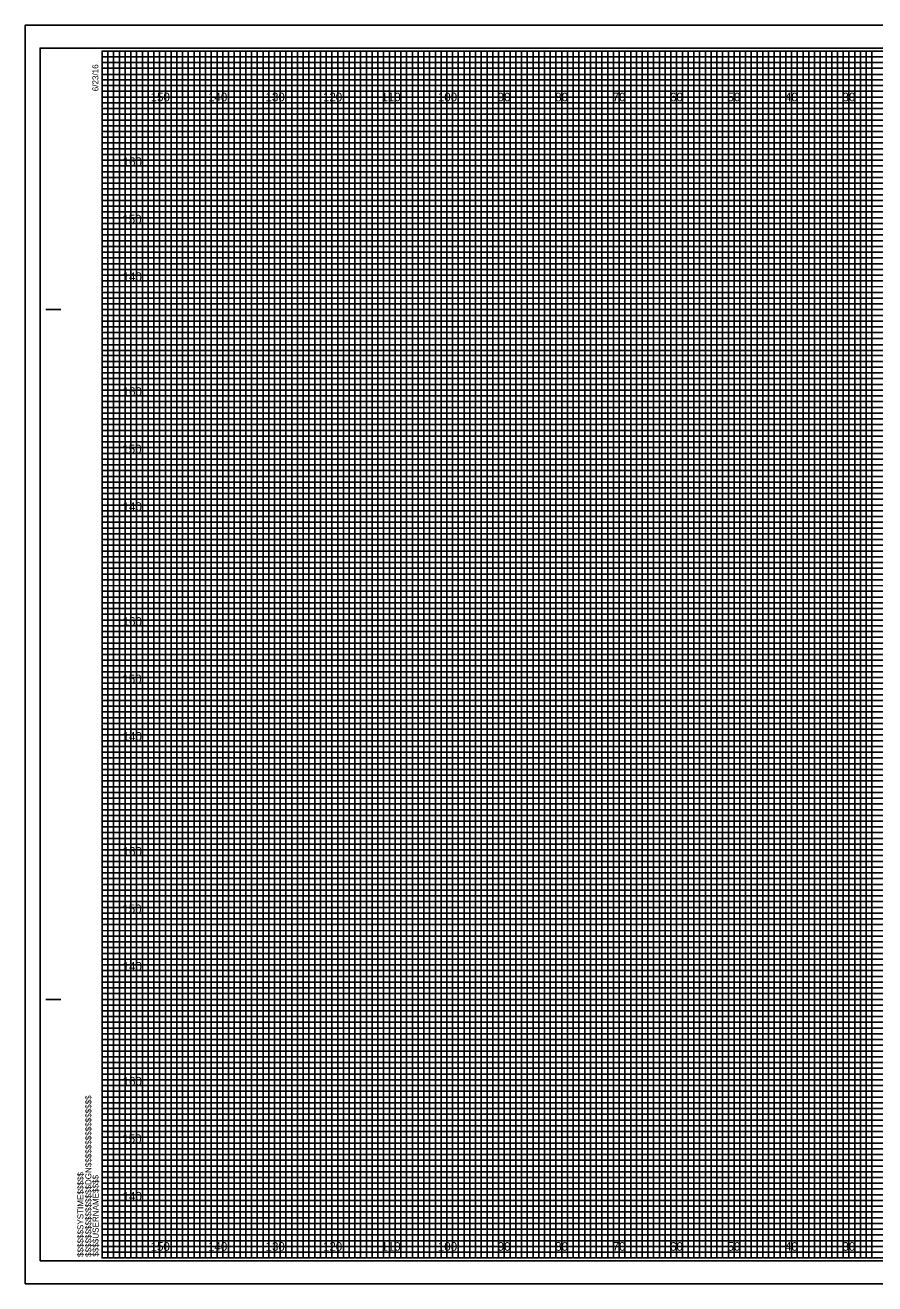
# Model space of a CAD drawing. Extents: x -13 to 323, y -5 to 4834.
# Drawn here: x -13.4 to 134.5, y -4.5 to 214.5 of the extents above; entities that cross this region are included whole.
import ezdxf

# ---------------------------------------------------------------- set-up
doc = ezdxf.new("R2010")
doc.units = 0
for name, color, linetype in [('Exist Cross Section Cell', 7, 'Continuous'), ('Exist XS Center Line Elevation Label', 7, 'Continuous'), ('Exist XS Ground Line', 7, 'Continuous'), ('Prop CMT Pvmt Course 1', 7, 'Continuous'), ('Prop CMT Pvmt Course 2', 7, 'Continuous'), ('Prop CMT Pvmt Course 3', 7, 'Continuous'), ('Prop CMT Pvmt Surface Shoulder', 7, 'Continuous'), ('Prop CMT Shld Paved Course 1', 7, 'Continuous'), ('Prop CMT Shld Paved Course 2', 7, 'Continuous'), ('Prop CMT Shld Paved Course 3', 7, 'Continuous'), ('Prop CMT Slope Grass', 7, 'Continuous')]:
    doc.layers.add(name, color=color, linetype=linetype)

msp = doc.modelspace()

# ---------------------------------------------------------------- linework, layer by layer
at = {"layer": 'Exist XS Center Line Elevation Label'}
for points in [[(0, 210), (5, 210), (5, 0), (15, 0), (15, 210), (25, 210), (25, 0), (35, 0), (35, 210), (45, 210), (45, 0), (55, 0), (55, 210), (65, 210), (65, 0), (75, 0), (75, 210), (85, 210), (85, 0), (95, 0), (95, 210), (105, 210), (105, 0), (115, 0), (115, 210), (125, 210), (125, 0), (135, 0)], [(0, 205), (275, 205)], [(0, 185), (320, 185), (320, 195), (0, 195)], [(0, 165), (320, 165), (320, 175), (0, 175)], [(0, 145), (320, 145), (320, 155), (0, 155)], [(0, 125), (320, 125), (320, 135), (0, 135)], [(0, 105), (320, 105), (320, 115), (0, 115)], [(0, 85), (320, 85), (320, 95), (0, 95)], [(0, 65), (320, 65), (320, 75), (0, 75)], [(0, 45), (320, 45), (320, 55), (0, 55)], [(0, 25), (320, 25), (320, 35), (0, 35)], [(0, 5), (320, 5), (320, 15), (0, 15)]]:
    msp.add_lwpolyline(points, dxfattribs=at)
at = {"layer": 'Exist XS Ground Line'}
for p, q in [((10, 210), (0, 210)), ((10, 0), (10, 210)), ((30, 210), (20, 210)), ((20, 210), (20, 0)), ((30, 0), (30, 210)), ((50, 210), (40, 210)), ((40, 210), (40, 0)), ((50, 0), (50, 210)), ((70, 210), (60, 210)), ((60, 210), (60, 0)), ((70, 0), (70, 210)), ((90, 210), (80, 210)), ((80, 210), (80, 0)), ((90, 0), (90, 210)), ((110, 210), (100, 210)), ((100, 210), (100, 0)), ((110, 0), (110, 210)), ((130, 210), (120, 210)), ((120, 210), (120, 0)), ((130, 0), (130, 210)), ((20, 0), (10, 0)), ((40, 0), (30, 0)), ((60, 0), (50, 0)), ((80, 0), (70, 0)), ((100, 0), (90, 0)), ((120, 0), (110, 0)), ((140, 0), (130, 0))]:
    msp.add_line(p, q, dxfattribs=at)
for points in [[(0, 200), (320, 200), (320, 190), (0, 190)], [(0, 180), (320, 180), (320, 170), (0, 170)], [(0, 160), (320, 160), (320, 150), (0, 150)], [(0, 140), (320, 140), (320, 130), (0, 130)], [(0, 120), (320, 120), (320, 110), (0, 110)], [(0, 100), (320, 100), (320, 90), (0, 90)], [(0, 80), (320, 80), (320, 70), (0, 70)], [(0, 60), (320, 60), (320, 50), (0, 50)], [(0, 40), (320, 40), (320, 30), (0, 30)], [(0, 20), (320, 20), (320, 10), (0, 10)]]:
    msp.add_lwpolyline(points, dxfattribs=at)
at = {"layer": 'Prop CMT Pvmt Course 1'}
for points in [[(0, 0), (1, 0), (1, 210), (2, 210), (2, 0)], [(2, 0), (3, 0), (3, 210), (4, 210), (4, 0)], [(5, 0), (6, 0), (6, 210), (7, 210), (7, 0)], [(7, 0), (8, 0), (8, 210), (9, 210), (9, 0)], [(10, 0), (11, 0), (11, 210), (12, 210), (12, 0)], [(12, 0), (13, 0), (13, 210), (14, 210), (14, 0)], [(15, 0), (16, 0), (16, 210), (17, 210), (17, 0)], [(17, 0), (18, 0), (18, 210), (19, 210), (19, 0)], [(20, 0), (21, 0), (21, 210), (22, 210), (22, 0)], [(22, 0), (23, 0), (23, 210), (24, 210), (24, 0)], [(25, 0), (26, 0), (26, 210), (27, 210), (27, 0)], [(27, 0), (28, 0), (28, 210), (29, 210), (29, 0)], [(30, 0), (31, 0), (31, 210), (32, 210), (32, 0)], [(32, 0), (33, 0), (33, 210), (34, 210), (34, 0)], [(35, 0), (36, 0), (36, 210), (37, 210), (37, 0)], [(37, 0), (38, 0), (38, 210), (39, 210), (39, 0)], [(40, 0), (41, 0), (41, 210), (42, 210), (42, 0)], [(42, 0), (43, 0), (43, 210), (44, 210), (44, 0)], [(45, 0), (46, 0), (46, 210), (47, 210), (47, 0)], [(47, 0), (48, 0), (48, 210), (49, 210), (49, 0)], [(50, 0), (51, 0), (51, 210), (52, 210), (52, 0)], [(52, 0), (53, 0), (53, 210), (54, 210), (54, 0)], [(55, 0), (56, 0), (56, 210), (57, 210), (57, 0)], [(57, 0), (58, 0), (58, 210), (59, 210), (59, 0)], [(60, 0), (61, 0), (61, 210), (62, 210), (62, 0)], [(62, 0), (63, 0), (63, 210), (64, 210), (64, 0)], [(65, 0), (66, 0), (66, 210), (67, 210), (67, 0)], [(67, 0), (68, 0), (68, 210), (69, 210), (69, 0)], [(70, 0), (71, 0), (71, 210), (72, 210), (72, 0)], [(72, 0), (73, 0), (73, 210), (74, 210), (74, 0)], [(75, 0), (76, 0), (76, 210), (77, 210), (77, 0)], [(77, 0), (78, 0), (78, 210), (79, 210), (79, 0)], [(80, 0), (81, 0), (81, 210), (82, 210), (82, 0)], [(82, 0), (83, 0), (83, 210), (84, 210), (84, 0)], [(85, 0), (86, 0), (86, 210), (87, 210), (87, 0)], [(87, 0), (88, 0), (88, 210), (89, 210), (89, 0)], [(90, 0), (91, 0), (91, 210), (92, 210), (92, 0)], [(92, 0), (93, 0), (93, 210), (94, 210), (94, 0)], [(95, 0), (96, 0), (96, 210), (97, 210), (97, 0)], [(97, 0), (98, 0), (98, 210), (99, 210), (99, 0)], [(100, 0), (101, 0), (101, 210), (102, 210), (102, 0)], [(102, 0), (103, 0), (103, 210), (104, 210), (104, 0)], [(105, 0), (106, 0), (106, 210), (107, 210), (107, 0)], [(107, 0), (108, 0), (108, 210), (109, 210), (109, 0)], [(110, 0), (111, 0), (111, 210), (112, 210), (112, 0)], [(112, 0), (113, 0), (113, 210), (114, 210), (114, 0)], [(115, 0), (116, 0), (116, 210), (117, 210), (117, 0)], [(117, 0), (118, 0), (118, 210), (119, 210), (119, 0)], [(120, 0), (121, 0), (121, 210), (122, 210), (122, 0)], [(122, 0), (123, 0), (123, 210), (124, 210), (124, 0)], [(125, 0), (126, 0), (126, 210), (127, 210), (127, 0)], [(127, 0), (128, 0), (128, 210), (129, 210), (129, 0)], [(130, 0), (131, 0), (131, 210), (132, 210), (132, 0)], [(132, 0), (133, 0), (133, 210), (134, 210), (134, 0)]]:
    msp.add_lwpolyline(points, dxfattribs=at)
at = {"layer": 'Prop CMT Pvmt Course 2'}
for p, q in [((323.3, 214.5), (-13.4, 214.5)), ((-13.4, 214.5), (-13.4, -4.5)), ((-13.4, -4.5), (323.3, -4.5))]:
    msp.add_line(p, q, dxfattribs=at)
at = {"layer": 'Prop CMT Pvmt Surface Shoulder'}
for p, q in [((-9.8, 165), (-7.3, 165)), ((-9.7, 165), (-7.2, 165)), ((-9.8, 45), (-7.3, 45)), ((-9.7, 45), (-7.2, 45)), ((0, 0), (0, 0)), ((0, 0), (0, 0)), ((0, 0), (0, 0)), ((0, 0), (0, 0)), ((0, 0), (0, 0)), ((0, 0), (0, 0)), ((0, 0), (0, 0))]:
    msp.add_line(p, q, dxfattribs=at)
msp.add_lwpolyline([(320, 210), (0, 210), (0, 0), (320, 0)], close=True, dxfattribs=at)
at = {"layer": 'Prop CMT Shld Paved Course 1'}
msp.add_lwpolyline([(-13.4, -4.5), (323.3, -4.5), (323.3, 214.5), (-13.4, 214.5)], close=True, dxfattribs=at)
at = {"layer": 'Prop CMT Shld Paved Course 2'}
msp.add_lwpolyline([(-10.8, -0.5), (322.4, -0.5), (322.4, 210.5), (-10.8, 210.5)], close=True, dxfattribs=at)
at = {"layer": 'Prop CMT Shld Paved Course 3'}
for p, q in [((10, 0), (10, 210)), ((20, 0), (20, 210)), ((30, 0), (30, 210)), ((40, 0), (40, 210)), ((50, 0), (50, 210)), ((60, 0), (60, 210)), ((70, 0), (70, 210)), ((80, 0), (80, 210)), ((90, 0), (90, 210)), ((100, 0), (100, 210)), ((110, 0), (110, 210)), ((120, 0), (120, 210)), ((130, 0), (130, 210)), ((0, 200), (320, 200)), ((0, 190), (320, 190)), ((0, 180), (320, 180)), ((0, 170), (320, 170)), ((0, 160), (320, 160)), ((0, 150), (320, 150)), ((0, 140), (320, 140)), ((0, 130), (320, 130)), ((0, 120), (320, 120)), ((0, 110), (320, 110)), ((0, 100), (320, 100)), ((0, 90), (320, 90)), ((0, 80), (320, 80)), ((0, 70), (320, 70)), ((0, 60), (320, 60)), ((0, 50), (320, 50)), ((0, 40), (320, 40)), ((0, 30), (320, 30)), ((0, 20), (320, 20)), ((0, 10), (320, 10))]:
    msp.add_line(p, q, dxfattribs=at)
at = {"layer": 'Prop CMT Slope Grass'}
for p, q in [((0, 209), (260, 209)), ((260, 207.98), (0, 207.98)), ((0, 207.98), (0, 207)), ((0, 207), (260, 207)), ((260, 205.89), (0, 205.89)), ((0, 205.89), (0, 204)), ((0, 204), (320, 204))]:
    msp.add_line(p, q, dxfattribs=at)
for points in [[(0, 203), (270, 203), (320, 203), (320, 202), (0, 202)], [(0, 201), (320, 201), (320, 199), (0, 199)], [(0, 198), (320, 198), (320, 197), (0, 196.98)], [(0, 196), (320, 196), (320, 194), (0, 194)], [(0, 193), (320, 193), (320, 192), (0, 192)], [(0, 191), (320, 191), (320, 189), (0, 189)], [(0, 188), (320, 188), (320, 187), (0, 187)], [(0, 186), (320, 186), (320, 184), (0, 184)], [(0, 183), (320, 183), (320, 182), (0, 182)], [(0, 181), (320, 181), (320, 179), (0, 179)], [(0, 178), (320, 178), (320, 177), (0, 177)], [(0, 176), (320, 176), (320, 173.95), (320, 173), (320, 172), (0, 172)], [(0, 174), (320, 174), (320, 173), (0, 173)], [(0, 171), (320, 171), (320, 169), (0, 169.03)], [(0, 169.03), (320, 169), (320, 168), (0, 168)], [(0, 167), (320, 167), (320, 166), (0, 166)], [(0, 164), (320, 164), (320, 163), (0, 163)], [(0, 162), (320, 162), (320, 161), (0, 161)], [(-0.07, 158.89), (320, 158.89), (320, 157.88), (-0.07, 157.88)], [(0, 157), (320, 157), (320, 156), (0, 156)], [(0, 154), (320, 154), (320, 153), (0, 153)], [(0, 152), (320, 152), (320, 151), (0, 151)], [(0, 149), (320, 149), (320, 148), (0, 148)], [(0, 147), (320, 147), (320, 146), (0, 146)], [(0, 144), (320, 144), (320, 143), (0, 143)], [(0, 142), (320, 142), (320, 141), (0, 141)], [(0, 139), (320, 139), (319.99, 137.98), (0, 138)], [(0, 137), (320, 137), (320, 136), (0, 136)], [(0, 134), (320, 134), (320, 133), (0, 133)], [(0, 132), (320, 132), (320, 131), (0, 131)], [(0, 129), (320, 129), (320, 128), (0, 128)], [(0, 127), (320, 127), (320, 126), (0, 126)], [(0, 124), (320, 124), (320, 123), (0, 123)], [(0, 122), (320, 122), (320, 121), (0, 121)], [(0, 119), (320, 119), (320, 118), (0, 118)], [(0, 116.99), (320.07, 116.91), (320, 116), (0, 116)], [(0, 114), (320, 114), (320, 113), (0, 113)], [(0, 112), (320, 112), (320, 111), (0, 111)], [(0, 109), (320, 109), (320, 108), (0, 108)], [(0, 107), (320, 107), (320, 106), (0, 106)], [(0, 104), (320, 104), (320, 103), (0, 103)], [(0, 102), (320, 102), (320, 101), (0, 101)], [(0, 99), (320, 99), (320, 98), (0, 98)], [(0, 97), (320, 97), (320, 96), (0, 96)], [(0, 94), (320, 94), (320, 93), (0, 93)], [(0, 92), (320, 92), (320, 91), (0, 91)], [(0, 89), (320, 89), (320, 88), (0, 88)], [(0, 87), (320, 87), (320, 86), (0, 86)], [(0, 84), (320, 84), (320, 83), (0, 83)], [(0, 82), (320, 82), (320, 81), (0, 81)], [(0, 79), (320, 79), (319.99, 77.98), (0, 78)], [(0, 77), (320, 77), (320, 76), (0, 76)], [(0, 74), (320, 74), (320, 73), (0, 73)], [(0, 72), (320, 72), (320, 71), (0, 71)], [(0, 69), (320, 69), (320, 68), (0, 68)], [(0, 67), (320, 67), (320, 66), (0, 66)], [(0, 64), (320, 64), (320, 63), (0, 63)], [(0, 62), (320, 62), (320, 61), (0, 61)], [(0, 59), (320, 59), (320, 58), (0, 58)], [(0, 56.99), (320.07, 56.91), (320, 56), (0, 56)], [(0, 54), (320, 54), (320, 53), (0, 53)], [(0, 52), (320, 52), (320, 51), (0, 51)], [(0, 49), (320, 49), (320, 48), (0, 48)], [(0, 47), (320, 47), (320, 46), (0, 46)], [(0, 44), (320, 44), (320, 43), (0, 43)], [(0, 42), (320, 42), (320, 41), (0, 41)], [(0, 39), (320, 39), (320, 38), (0, 38)], [(0, 37), (320, 37), (320, 36), (0, 36)], [(0, 34), (320, 34), (320, 33), (0, 33)], [(0, 32), (320, 32), (320, 31), (0, 31)], [(0, 29), (320, 29), (320, 28), (0, 28)], [(0, 27), (320, 27), (320, 26), (0, 26)], [(0, 24), (320, 24), (320, 23), (0, 23)], [(0, 22), (320, 22), (320, 21), (0, 21)], [(0, 19), (320, 19), (320, 18), (0, 18)], [(0, 17), (320, 17), (320, 16), (0, 16)], [(0, 14), (320, 14), (320, 13), (0, 13)], [(0, 12), (320, 12), (320, 11), (0, 11)], [(0, 9), (320, 9), (320, 8), (0, 8)], [(0, 7), (320, 7), (320, 6), (0, 6)], [(0, 4), (320, 4), (320, 3), (0, 3)], [(0, 2), (320, 2), (320, 1), (0, 1)]]:
    msp.add_lwpolyline(points, dxfattribs=at)

# ---------------------------------------------------------------- texts
at = {"layer": 'Exist Cross Section Cell'}
for s, p in [('150', (8.44, 201.25)), ('140', (18.44, 201.25)), ('130', (28.44, 201.25)), ('120', (38.44, 201.25)), ('110', (48.62, 201.25)), ('100', (58.44, 201.25)), ('90', (68.86, 201.25)), ('80', (78.86, 201.25)), ('70', (88.86, 201.25)), ('60', (98.86, 201.25)), ('50', (108.86, 201.25)), ('40', (118.86, 201.25)), ('30', (128.86, 201.25)), ('150', (8.44, 1.25)), ('140', (18.44, 1.25)), ('130', (28.44, 1.25)), ('120', (38.44, 1.25)), ('110', (48.62, 1.25)), ('100', (58.44, 1.25)), ('90', (68.86, 1.25)), ('80', (78.86, 1.25)), ('70', (88.86, 1.25)), ('60', (98.86, 1.25)), ('50', (108.86, 1.25)), ('40', (118.86, 1.25)), ('30', (128.86, 1.25))]:
    msp.add_text(s, height=1.5, dxfattribs=at).set_placement(p)
at = {"layer": 'Prop CMT Pvmt Course 3'}
for s, p in [('160', (3.57, 190)), ('150', (3.52, 180)), ('140', (3.57, 170)), ('160', (3.57, 150)), ('150', (3.52, 140)), ('140', (3.57, 130)), ('160', (3.57, 110)), ('150', (3.52, 100)), ('140', (3.57, 90)), ('160', (3.57, 70)), ('150', (3.52, 60)), ('140', (3.57, 50)), ('160', (3.57, 30)), ('150', (3.52, 20)), ('140', (3.57, 10))]:
    msp.add_text(s, height=1.5, dxfattribs=at).set_placement(p)
at = {"layer": 'Prop CMT Pvmt Surface Shoulder'}
for s, p in [('6/23/16', (-0.65, 203)), ('$$$$$$$$$$$$$$$$DGN$$$$$$$$$$$$$$$$', (-1.88, 0.18)), ('$$$$$$SYSTIME$$$$$', (-3.26, 0.18)), ('$$$$USERNAME$$$$', (-0.62, 0.23))]:
    msp.add_text(s, height=1.05, rotation=90, dxfattribs=at).set_placement(p)

doc.saveas('drawing.dxf')
